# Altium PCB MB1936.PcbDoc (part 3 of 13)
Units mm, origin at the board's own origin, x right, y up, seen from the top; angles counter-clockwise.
Board outline 172 x 137 mm, 6 copper layers (Top Layer, Signal Layer 1, Signal Layer 2, Signal Layer 3, Signal Layer 4, Bottom Layer), stack 1.549 mm thick; 859 components, 672 nets, 3477 pads, 2222 vias.
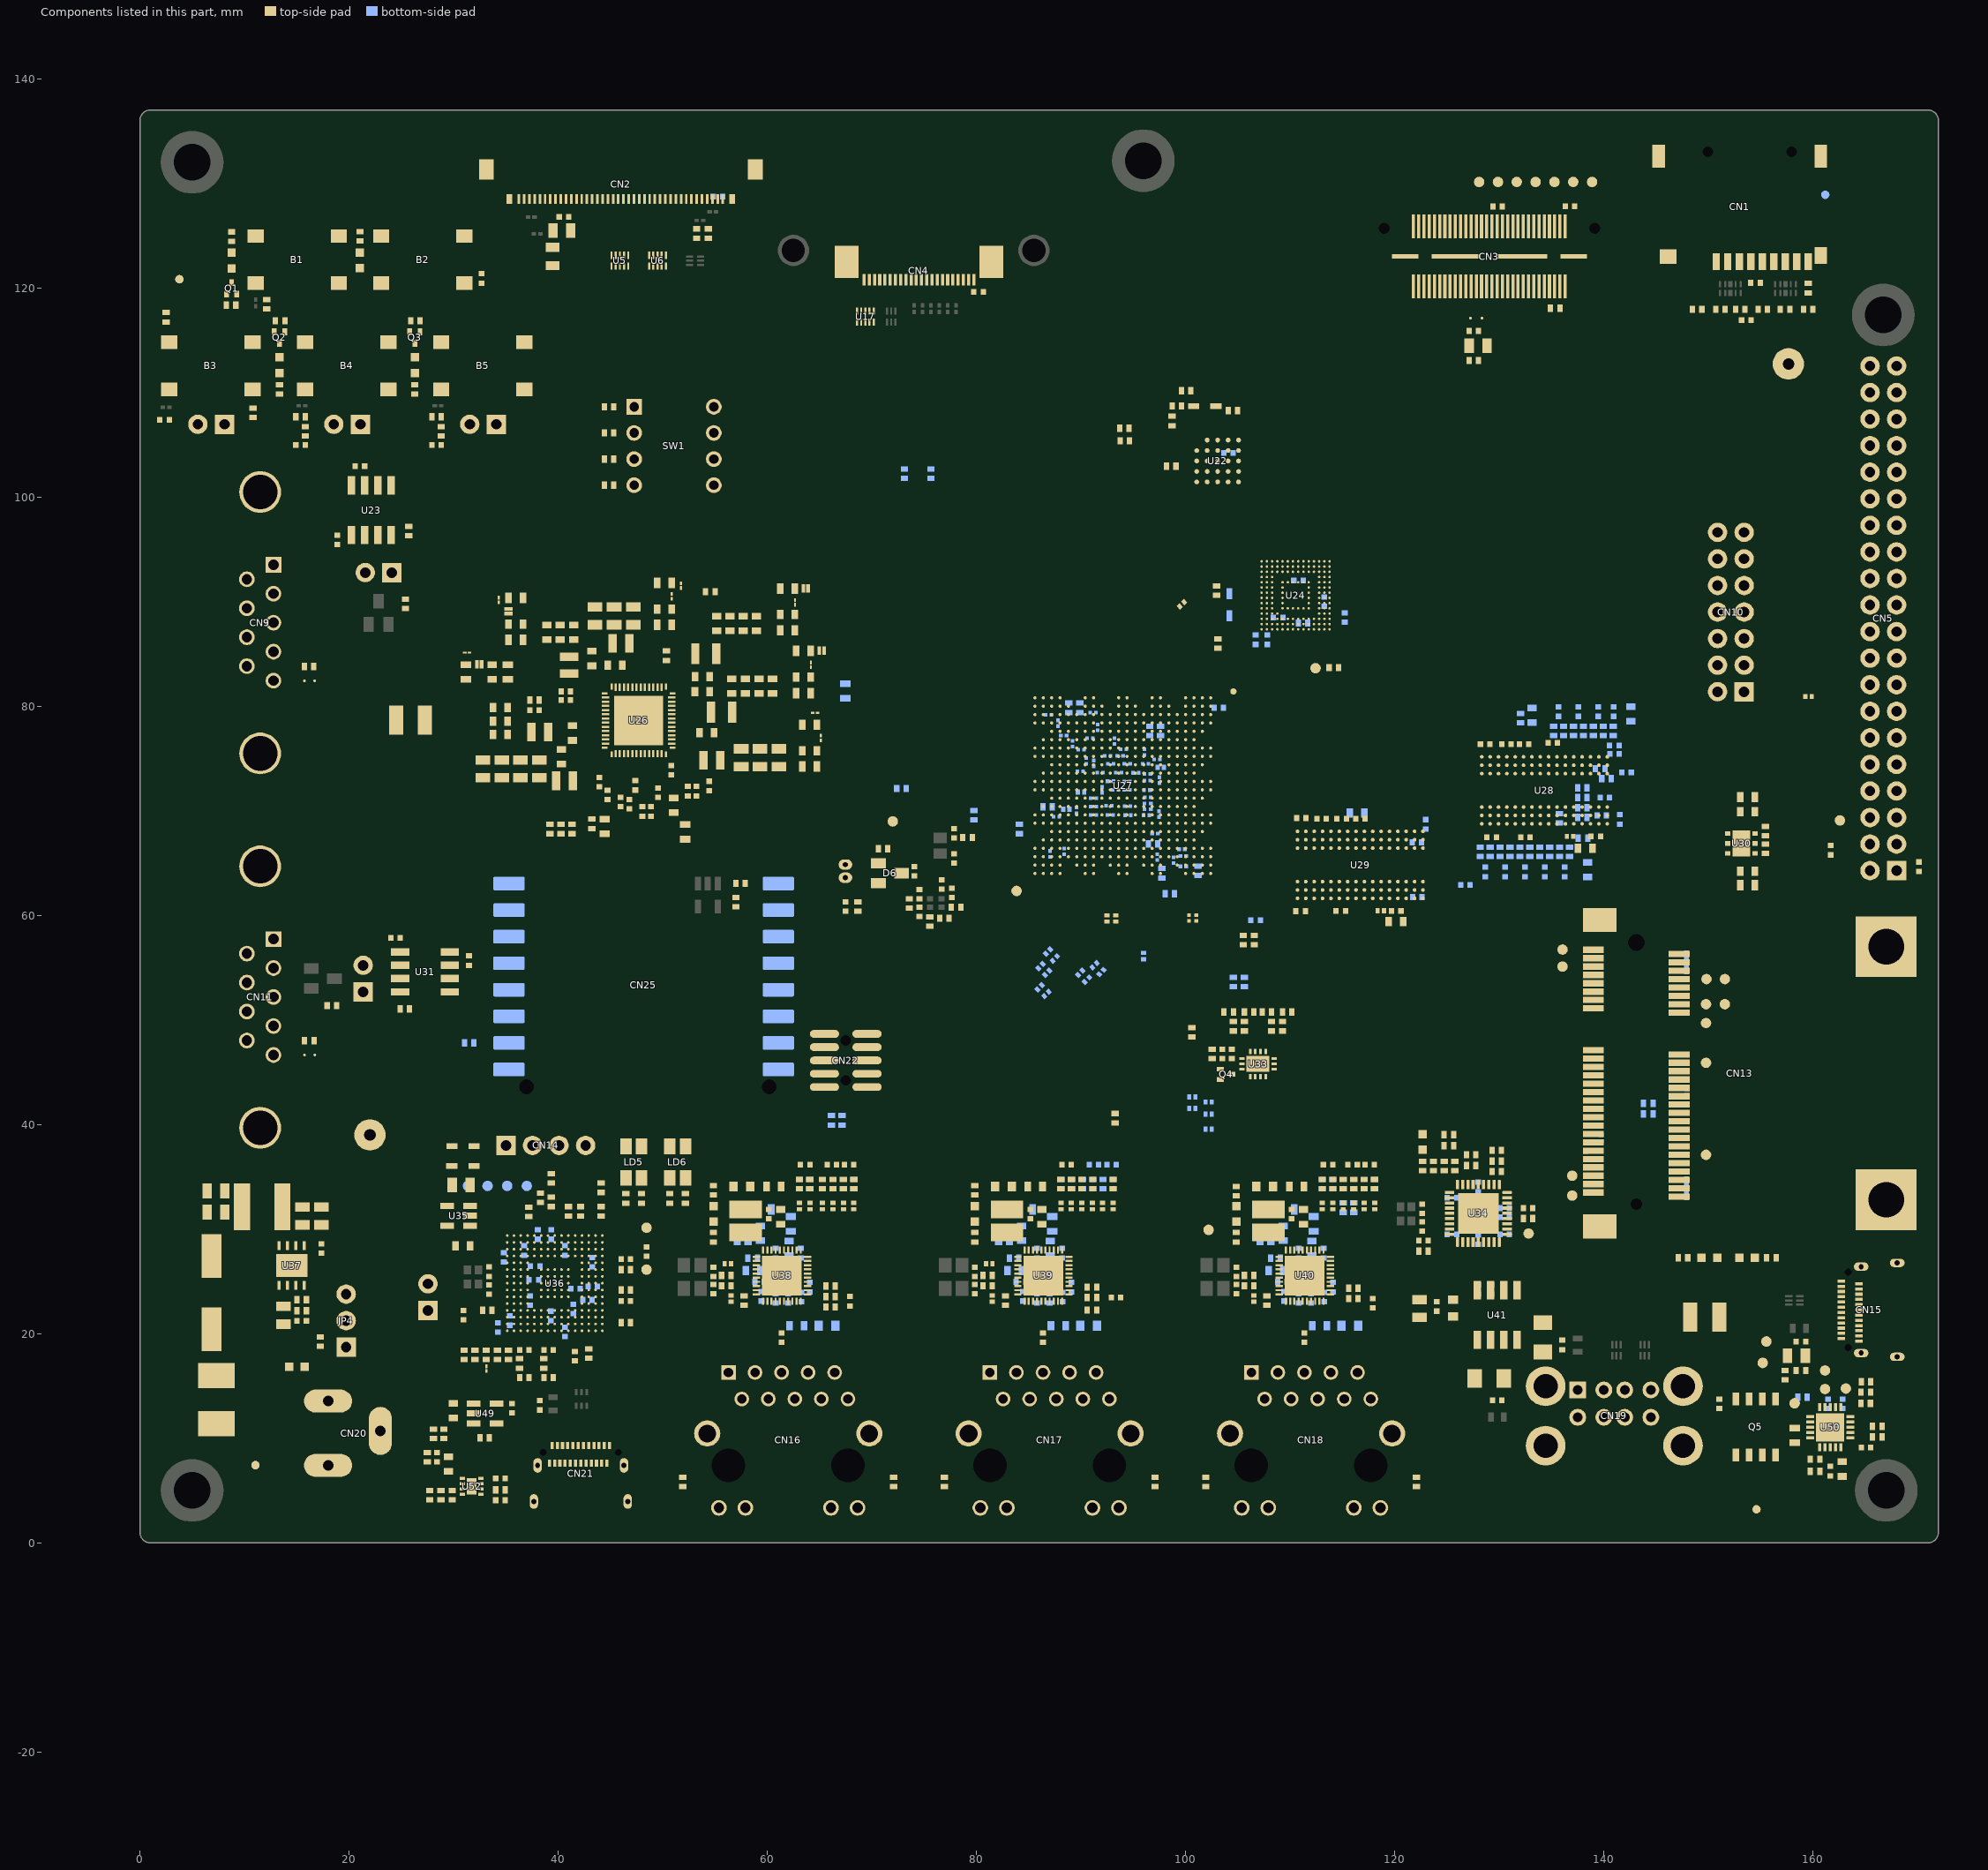
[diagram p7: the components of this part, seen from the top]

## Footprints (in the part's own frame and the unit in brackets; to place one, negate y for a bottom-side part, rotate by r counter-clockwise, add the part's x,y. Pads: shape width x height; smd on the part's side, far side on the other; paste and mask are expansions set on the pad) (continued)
ESD_UQFN-10L_2P25X1P4_P040 [mm] "MCD-03059"
  rect 0.2x0.7 smd mask+0.05: 1(-0.8,-0.525) 2(-0.4,-0.525) 3(0,-0.525) 4(0.4,-0.525) 5(0.8,-0.525) 6(0.8,0.525) 7(0.4,0.525) 8(0,0.525) 9(-0.4,0.525) 10(-0.8,0.525)
  body extent -1.12,-0.7 1.12,0.7, height 0.51
FIL_0603_H0P65 [mm]
  rect 0.8x0.95 smd mask+0.05: 1(-0.8,0) 2(0.8,0)
  silkscreen extent -1.33,-0.6 1.33,0.6, body extent -0.87,-0.47 0.87,0.47, height 0.65
ICC_BGA24_5X5-BALL-ARRAY_6X8_P1 [mm]
  round 0.45 smd mask+0.05: A2(-1,2) A3(0,2) A4(1,2) A5(2,2) B1(-2,1) B2(-1,1) B3(0,1) B4(1,1) B5(2,1) C1(-2,0) C2(-1,0) C3(0,0) C4(1,0) C5(2,0) D1(-2,-1) D2(-1,-1) D3(0,-1) D4(1,-1) D5(2,-1) E1(-2,-2) E2(-1,-2) E3(0,-2) E4(1,-2) E5(2,-2)
  silkscreen extent -3.05,-4.05 3.05,4.05, body extent -3.05,-4.05 3.05,4.05, height 1.2
ICC_DFN6-EPAD_3X3_P095 [mm]
  rect 0.45x0.5 smd mask+0.05: 1(-0.95,-1.3) 2(0,-1.3) 3(0.95,-1.3) 4(0.95,1.3) 5(0,1.3) 6(-0.95,1.3)
  rect 2.5x1.7 smd mask+0.05: EP(0,0)
  silkscreen extent -1.55,-1.55 1.55,1.55, body extent -1.55,-1.55 1.55,1.55, height 1
ICC_FBGA96_TB_7P5X13_P080 [mm] "MCD-03523"
  round 0.35 smd mask+0.05: A1(-3.2,6) A2(-2.4,6) A3(-1.6,6) A7(1.6,6) A8(2.4,6) A9(3.2,6) B1(-3.2,5.2) B2(-2.4,5.2) B3(-1.6,5.2) B7(1.6,5.2) B8(2.4,5.2) B9(3.2,5.2) C1(-3.2,4.4) C2(-2.4,4.4) C3(-1.6,4.4) C7(1.6,4.4) C8(2.4,4.4) C9(3.2,4.4) D1(-3.2,3.6) D2(-2.4,3.6) D3(-1.6,3.6) D7(1.6,3.6) D8(2.4,3.6) D9(3.2,3.6) E1(-3.2,2.8) E2(-2.4,2.8) E3(-1.6,2.8) E7(1.6,2.8) E8(2.4,2.8) E9(3.2,2.8) F1(-3.2,2) F2(-2.4,2) F3(-1.6,2) F7(1.6,2) F8(2.4,2) F9(3.2,2) G1(-3.2,1.2) G2(-2.4,1.2) G3(-1.6,1.2) G7(1.6,1.2) G8(2.4,1.2) G9(3.2,1.2) H1(-3.2,0.4) H2(-2.4,0.4) H3(-1.6,0.4) H7(1.6,0.4) H8(2.4,0.4) H9(3.2,0.4) J1(-3.2,-0.4) J2(-2.4,-0.4) J3(-1.6,-0.4) J7(1.6,-0.4) J8(2.4,-0.4) J9(3.2,-0.4) K1(-3.2,-1.2) K2(-2.4,-1.2) K3(-1.6,-1.2) K7(1.6,-1.2) K8(2.4,-1.2) K9(3.2,-1.2) L1(-3.2,-2) L2(-2.4,-2) L3(-1.6,-2) L7(1.6,-2) L8(2.4,-2) L9(3.2,-2) M1(-3.2,-2.8) M2(-2.4,-2.8) M3(-1.6,-2.8) M7(1.6,-2.8) M8(2.4,-2.8) M9(3.2,-2.8) N1(-3.2,-3.6) N2(-2.4,-3.6) N3(-1.6,-3.6) N7(1.6,-3.6) N8(2.4,-3.6) N9(3.2,-3.6) P1(-3.2,-4.4) P2(-2.4,-4.4) P3(-1.6,-4.4) P7(1.6,-4.4) P8(2.4,-4.4) P9(3.2,-4.4) R1(-3.2,-5.2) R2(-2.4,-5.2) R3(-1.6,-5.2) R7(1.6,-5.2) R8(2.4,-5.2) R9(3.2,-5.2) T1(-3.2,-6) T2(-2.4,-6) T3(-1.6,-6) T7(1.6,-6) T8(2.4,-6) T9(3.2,-6)
  silkscreen extent -3.93,-6.55 3.8,6.68, body extent -3.8,-6.55 3.8,6.55, height 1.21
ICC_LFBGA436_18X18_P080_H1P70_STM32MP257_CODE-B0D1 [mm] "MCD02000"
  round 0.3 smd paste+0.025 mask+0.05: A1(-8.4,8.4) A2(-7.6,8.4) A3(-6.8,8.4) A4(-6,8.4) A7(-3.6,8.4) A8(-2.8,8.4) A11(-0.4,8.4) A12(0.4,8.4) A15(2.8,8.4) A16(3.6,8.4) A19(6,8.4) A20(6.8,8.4) A21(7.6,8.4) A22(8.4,8.4) AA1(-8.4,-7.6) AA2(-7.6,-7.6) AA3(-6.8,-7.6) AA4(-6,-7.6) AA6(-4.4,-7.6) AA7(-3.6,-7.6) AA8(-2.8,-7.6) AA10(-1.2,-7.6) AA11(-0.4,-7.6) AA12(0.4,-7.6) AA14(2,-7.6) AA15(2.8,-7.6) AA16(3.6,-7.6) AA18(5.2,-7.6) AA19(6,-7.6) AA20(6.8,-7.6) AA21(7.6,-7.6) AA22(8.4,-7.6) AB1(-8.4,-8.4) AB2(-7.6,-8.4) AB3(-6.8,-8.4) AB4(-6,-8.4) AB7(-3.6,-8.4) AB8(-2.8,-8.4) AB11(-0.4,-8.4) AB12(0.4,-8.4) AB15(2.8,-8.4) AB16(3.6,-8.4) AB19(6,-8.4) AB20(6.8,-8.4) AB21(7.6,-8.4) AB22(8.4,-8.4) B1(-8.4,7.6) B2(-7.6,7.6) B3(-6.8,7.6) B4(-6,7.6) B5(-5.2,7.6) B7(-3.6,7.6) B8(-2.8,7.6) B9(-2,7.6) B11(-0.4,7.6) B12(0.4,7.6) B13(1.2,7.6) B15(2.8,7.6) B16(3.6,7.6) B17(4.4,7.6) B19(6,7.6) B20(6.8,7.6) B21(7.6,7.6) B22(8.4,7.6) C1(-8.4,6.8) C2(-7.6,6.8) C3(-6.8,6.8) C4(-6,6.8) C5(-5.2,6.8) C6(-4.4,6.8) C7(-3.6,6.8) C8(-2.8,6.8) C9(-2,6.8) C10(-1.2,6.8) C11(-0.4,6.8) C12(0.4,6.8) C13(1.2,6.8) C14(2,6.8) C15(2.8,6.8) C16(3.6,6.8) C17(4.4,6.8) C18(5.2,6.8) C19(6,6.8) C20(6.8,6.8) C21(7.6,6.8) C22(8.4,6.8) D1(-8.4,6) D2(-7.6,6) D3(-6.8,6) D4(-6,6) D5(-5.2,6) D6(-4.4,6) D7(-3.6,6) D8(-2.8,6) D9(-2,6) D10(-1.2,6) D11(-0.4,6) D12(0.4,6) D13(1.2,6) D14(2,6) D15(2.8,6) D16(3.6,6) D17(4.4,6) D18(5.2,6) D19(6,6) D20(6.8,6) D21(7.6,6) D22(8.4,6) E3(-6.8,5.2) E4(-6,5.2) E5(-5.2,5.2) E6(-4.4,5.2) E7(-3.6,5.2) E8(-2.8,5.2) E9(-2,5.2) E10(-1.2,5.2) E11(-0.4,5.2) E12(0.4,5.2) E13(1.2,5.2) E14(2,5.2) E15(2.8,5.2) E16(3.6,5.2) E17(4.4,5.2) E18(5.2,5.2) E19(6,5.2) E20(6.8,5.2) E21(7.6,5.2) F2(-7.6,4.4) F3(-6.8,4.4) F4(-6,4.4) F5(-5.2,4.4) F6(-4.4,4.4) F7(-3.6,4.4) F8(-2.8,4.4) F9(-2,4.4) F10(-1.2,4.4) F11(-0.4,4.4) F12(0.4,4.4) F13(1.2,4.4) F14(2,4.4) F15(2.8,4.4) F16(3.6,4.4) F17(4.4,4.4) F18(5.2,4.4) F19(6,4.4) F20(6.8,4.4) G1(-8.4,3.6) G2(-7.6,3.6) G3(-6.8,3.6) G4(-6,3.6) G5(-5.2,3.6) G6(-4.4,3.6) G7(-3.6,3.6) G8(-2.8,3.6) G9(-2,3.6) G10(-1.2,3.6) G11(-0.4,3.6) G12(0.4,3.6) G13(1.2,3.6) G14(2,3.6) G15(2.8,3.6) G16(3.6,3.6) G17(4.4,3.6) G18(5.2,3.6) G19(6,3.6) G20(6.8,3.6) G21(7.6,3.6) G22(8.4,3.6) H1(-8.4,2.8) H2(-7.6,2.8) H3(-6.8,2.8) H4(-6,2.8) H5(-5.2,2.8) H6(-4.4,2.8) H7(-3.6,2.8) H8(-2.8,2.8) H9(-2,2.8) H10(-1.2,2.8) H11(-0.4,2.8) H12(0.4,2.8) H13(1.2,2.8) H14(2,2.8) H15(2.8,2.8) H16(3.6,2.8) H17(4.4,2.8) H18(5.2,2.8) H19(6,2.8) H20(6.8,2.8) H21(7.6,2.8) H22(8.4,2.8) J3(-6.8,2) J4(-6,2) J5(-5.2,2) J6(-4.4,2) J7(-3.6,2) J8(-2.8,2) J9(-2,2) J10(-1.2,2) J11(-0.4,2) J12(0.4,2) J13(1.2,2) J14(2,2) J15(2.8,2) J16(3.6,2) J17(4.4,2) J18(5.2,2) J19(6,2) J20(6.8,2) J21(7.6,2) K2(-7.6,1.2) K3(-6.8,1.2) K4(-6,1.2) K5(-5.2,1.2) K6(-4.4,1.2) K7(-3.6,1.2) K8(-2.8,1.2) K9(-2,1.2) K10(-1.2,1.2) K11(-0.4,1.2) K12(0.4,1.2) K13(1.2,1.2) K14(2,1.2) K15(2.8,1.2) K16(3.6,1.2) K17(4.4,1.2) K18(5.2,1.2) K19(6,1.2) K20(6.8,1.2) L1(-8.4,0.4) L2(-7.6,0.4) L3(-6.8,0.4) L4(-6,0.4) L5(-5.2,0.4) L6(-4.4,0.4) L7(-3.6,0.4) L8(-2.8,0.4) L9(-2,0.4) L10(-1.2,0.4) L11(-0.4,0.4) L12(0.4,0.4) L13(1.2,0.4) L14(2,0.4) L15(2.8,0.4) L16(3.6,0.4) L17(4.4,0.4) L18(5.2,0.4) L19(6,0.4) L20(6.8,0.4) L21(7.6,0.4) L22(8.4,0.4) M1(-8.4,-0.4) M2(-7.6,-0.4) M3(-6.8,-0.4) M4(-6,-0.4) M5(-5.2,-0.4) M6(-4.4,-0.4) M7(-3.6,-0.4) M8(-2.8,-0.4) M9(-2,-0.4) M10(-1.2,-0.4) M11(-0.4,-0.4) M12(0.4,-0.4) M13(1.2,-0.4) M14(2,-0.4) M15(2.8,-0.4) M16(3.6,-0.4) M17(4.4,-0.4) M18(5.2,-0.4) M19(6,-0.4) M20(6.8,-0.4) M21(7.6,-0.4) M22(8.4,-0.4) N3(-6.8,-1.2) N4(-6,-1.2) N5(-5.2,-1.2) N6(-4.4,-1.2) N7(-3.6,-1.2) N8(-2.8,-1.2) N9(-2,-1.2) N10(-1.2,-1.2) N11(-0.4,-1.2) N12(0.4,-1.2) N13(1.2,-1.2) N14(2,-1.2) N15(2.8,-1.2) N16(3.6,-1.2) N17(4.4,-1.2) N18(5.2,-1.2) N19(6,-1.2) N20(6.8,-1.2) N21(7.6,-1.2) P2(-7.6,-2) P3(-6.8,-2) P4(-6,-2) P5(-5.2,-2) P6(-4.4,-2) P7(-3.6,-2) P8(-2.8,-2) P9(-2,-2) P10(-1.2,-2) P11(-0.4,-2) P12(0.4,-2) P13(1.2,-2) P14(2,-2) P15(2.8,-2) P16(3.6,-2) P17(4.4,-2) P18(5.2,-2) P19(6,-2) P20(6.8,-2) R1(-8.4,-2.8) R2(-7.6,-2.8) R3(-6.8,-2.8) R4(-6,-2.8) R5(-5.2,-2.8) R6(-4.4,-2.8) R7(-3.6,-2.8) R8(-2.8,-2.8) R9(-2,-2.8) R10(-1.2,-2.8) R11(-0.4,-2.8) R12(0.4,-2.8) R13(1.2,-2.8) R14(2,-2.8) R15(2.8,-2.8) R16(3.6,-2.8) R17(4.4,-2.8) R18(5.2,-2.8) R19(6,-2.8) R20(6.8,-2.8) R21(7.6,-2.8) R22(8.4,-2.8) T1(-8.4,-3.6) T2(-7.6,-3.6) T3(-6.8,-3.6) T4(-6,-3.6) T5(-5.2,-3.6) T6(-4.4,-3.6) T7(-3.6,-3.6) T8(-2.8,-3.6) T9(-2,-3.6) T10(-1.2,-3.6) T11(-0.4,-3.6) T12(0.4,-3.6) T13(1.2,-3.6) T14(2,-3.6) T15(2.8,-3.6) T16(3.6,-3.6) T17(4.4,-3.6) T18(5.2,-3.6) T19(6,-3.6) T20(6.8,-3.6) T21(7.6,-3.6) T22(8.4,-3.6) U3(-6.8,-4.4) U4(-6,-4.4) U5(-5.2,-4.4) U6(-4.4,-4.4) U7(-3.6,-4.4) U8(-2.8,-4.4) U9(-2,-4.4) U10(-1.2,-4.4) U11(-0.4,-4.4) U12(0.4,-4.4) U13(1.2,-4.4) U14(2,-4.4) U15(2.8,-4.4) U16(3.6,-4.4) U17(4.4,-4.4) U18(5.2,-4.4) U19(6,-4.4) U20(6.8,-4.4) U21(7.6,-4.4) V2(-7.6,-5.2) V3(-6.8,-5.2) V4(-6,-5.2) V5(-5.2,-5.2) V6(-4.4,-5.2) V7(-3.6,-5.2) V8(-2.8,-5.2) V9(-2,-5.2) V10(-1.2,-5.2) V11(-0.4,-5.2) V12(0.4,-5.2) V13(1.2,-5.2) V14(2,-5.2) V15(2.8,-5.2) V16(3.6,-5.2) V17(4.4,-5.2) V18(5.2,-5.2) V19(6,-5.2) V20(6.8,-5.2) W1(-8.4,-6) W2(-7.6,-6) W3(-6.8,-6) W4(-6,-6) W5(-5.2,-6) W6(-4.4,-6) W7(-3.6,-6) W8(-2.8,-6) W9(-2,-6) W10(-1.2,-6) W11(-0.4,-6) W12(0.4,-6) W13(1.2,-6) W14(2,-6) W15(2.8,-6) W16(3.6,-6) W17(4.4,-6) W18(5.2,-6) W19(6,-6) W20(6.8,-6) W21(7.6,-6) W22(8.4,-6) Y1(-8.4,-6.8) Y2(-7.6,-6.8) Y3(-6.8,-6.8) Y4(-6,-6.8) Y5(-5.2,-6.8) Y6(-4.4,-6.8) Y7(-3.6,-6.8) Y8(-2.8,-6.8) Y9(-2,-6.8) Y10(-1.2,-6.8) Y11(-0.4,-6.8) Y12(0.4,-6.8) Y13(1.2,-6.8) Y14(2,-6.8) Y15(2.8,-6.8) Y16(3.6,-6.8) Y17(4.4,-6.8) Y18(5.2,-6.8) Y19(6,-6.8) Y20(6.8,-6.8) Y21(7.6,-6.8) Y22(8.4,-6.8)
  silkscreen extent -9.25,-9.1 9.1,9.25, body extent -9.1,-9.1 9.1,9.1, height 1.7
ICC_P-WFBGA153_13X11P5_P050 [mm]
  round 0.23 smd mask+0.05: A1(-3.25,-3.25) A2(-3.25,-2.75) A3(-3.25,-2.25) A4(-3.25,-1.75) A5(-3.25,-1.25) A6(-3.25,-0.75) A7(-3.25,-0.25) A8(-3.25,0.25) A9(-3.25,0.75) A10(-3.25,1.25) A11(-3.25,1.75) A12(-3.25,2.25) A13(-3.25,2.75) A14(-3.25,3.25) B1(-2.75,-3.25) B2(-2.75,-2.75) B3(-2.75,-2.25) B4(-2.75,-1.75) B5(-2.75,-1.25) B6(-2.75,-0.75) B7(-2.75,-0.25) B8(-2.75,0.25) B9(-2.75,0.75) B10(-2.75,1.25) B11(-2.75,1.75) B12(-2.75,2.25) B13(-2.75,2.75) B14(-2.75,3.25) C1(-2.25,-3.25) C2(-2.25,-2.75) C3(-2.25,-2.25) C4(-2.25,-1.75) C5(-2.25,-1.25) C6(-2.25,-0.75) C7(-2.25,-0.25) C8(-2.25,0.25) C9(-2.25,0.75) C10(-2.25,1.25) C11(-2.25,1.75) C12(-2.25,2.25) C13(-2.25,2.75) C14(-2.25,3.25) D1(-1.75,-3.25) D2(-1.75,-2.75) D3(-1.75,-2.25) D4(-1.75,-1.75) D12(-1.75,2.25) D13(-1.75,2.75) D14(-1.75,3.25) E1(-1.25,-3.25) E2(-1.25,-2.75) E3(-1.25,-2.25) E5(-1.25,-1.25) E6(-1.25,-0.75) E7(-1.25,-0.25) E8(-1.25,0.25) E9(-1.25,0.75) E10(-1.25,1.25) E12(-1.25,2.25) E13(-1.25,2.75) E14(-1.25,3.25) F1(-0.75,-3.25) F2(-0.75,-2.75) F3(-0.75,-2.25) F5(-0.75,-1.25) F10(-0.75,1.25) F12(-0.75,2.25) F13(-0.75,2.75) F14(-0.75,3.25) G1(-0.25,-3.25) G2(-0.25,-2.75) G3(-0.25,-2.25) G5(-0.25,-1.25) G10(-0.25,1.25) G12(-0.25,2.25) G13(-0.25,2.75) G14(-0.25,3.25) H1(0.25,-3.25) H2(0.25,-2.75) H3(0.25,-2.25) H5(0.25,-1.25) H10(0.25,1.25) H12(0.25,2.25) H13(0.25,2.75) H14(0.25,3.25) J1(0.75,-3.25) J2(0.75,-2.75) J3(0.75,-2.25) J5(0.75,-1.25) J10(0.75,1.25) J12(0.75,2.25) J13(0.75,2.75) J14(0.75,3.25) K1(1.25,-3.25) K2(1.25,-2.75) K3(1.25,-2.25) K5(1.25,-1.25) K6(1.25,-0.75) K7(1.25,-0.25) K8(1.25,0.25) K9(1.25,0.75) K10(1.25,1.25) K12(1.25,2.25) K13(1.25,2.75) K14(1.25,3.25) L1(1.75,-3.25) L2(1.75,-2.75) L3(1.75,-2.25) L12(1.75,2.25) L13(1.75,2.75) L14(1.75,3.25) M1(2.25,-3.25) M2(2.25,-2.75) M3(2.25,-2.25) M4(2.25,-1.75) M5(2.25,-1.25) M6(2.25,-0.75) M7(2.25,-0.25) M8(2.25,0.25) M9(2.25,0.75) M10(2.25,1.25) M11(2.25,1.75) M12(2.25,2.25) M13(2.25,2.75) M14(2.25,3.25) N1(2.75,-3.25) N2(2.75,-2.75) N3(2.75,-2.25) N4(2.75,-1.75) N5(2.75,-1.25) N6(2.75,-0.75) N7(2.75,-0.25) N8(2.75,0.25) N9(2.75,0.75) N10(2.75,1.25) N11(2.75,1.75) N12(2.75,2.25) N13(2.75,2.75) N14(2.75,3.25) P1(3.25,-3.25) P2(3.25,-2.75) P3(3.25,-2.25) P4(3.25,-1.75) P5(3.25,-1.25) P6(3.25,-0.75) P7(3.25,-0.25) P8(3.25,0.25) P9(3.25,0.75) P10(3.25,1.25) P11(3.25,1.75) P12(3.25,2.25) P13(3.25,2.75) P14(3.25,3.25)
  silkscreen extent -6.78,-6.02 6.63,5.87, body extent -6.55,-5.8 6.55,5.8, height 1
ICC_QFN14-EPAD_3P2X2P5_P050 [mm] "MCD-02349"
  rect 0.25x0.5 smd mask+0.05: 1(-0.75,-1.2) 2(-0.25,-1.2) 3(0.25,-1.2) 4(0.75,-1.2) 8(0.75,1.2) 9(0.25,1.2) 10(-0.25,1.2) 11(-0.75,1.2)
  rect 0.5x0.25 smd mask+0.05: 5(1.55,-0.5) 6(1.55,0) 7(1.55,0.5) 12(-1.55,0.5) 13(-1.55,0) 14(-1.55,-0.5)
  rect 2.2x1.5 smd mask+0.05: 15(0,0)
  silkscreen extent -1.8,-1.45 1.63,1.28, body extent -1.63,-1.28 1.63,1.28, height 0.86
ICC_QFN20-EPAD_4X4_P050 [mm] "MCD-02130"
  rect 0.75x0.3 smd mask+0.05: 1(-1.925,1) 2(-1.925,0.5) 3(-1.925,0) 4(-1.925,-0.5) 5(-1.925,-1) 11(1.925,-1) 12(1.925,-0.5) 13(1.925,0) 14(1.925,0.5) 15(1.925,1)
  rect 0.3x0.75 smd mask+0.05: 6(-1,-1.925) 7(-0.5,-1.925) 8(0,-1.925) 9(0.5,-1.925) 10(1,-1.925) 16(1,1.925) 17(0.5,1.925) 18(0,1.925) 19(-0.5,1.925) 20(-1,1.925)
  rect 2.7x2.7 smd mask+0.05: 21(0,0)
  silkscreen extent -2.07,-2.07 2.07,2.07, body extent -2.13,-2.13 2.13,2.13, height 1.01
ICC_QFN36-EPAD_6X6_P050 [mm]
  rrect50% 0.3x0.9 smd mask+0.05: 1(-2,-2.75) 9(2,-2.75) 19(2,2.75) 27(-2,2.75)
  rect 0.3x0.9 smd mask+0.05: 2(-1.5,-2.75) 3(-1,-2.75) 4(-0.5,-2.75) 5(0,-2.75) 6(0.5,-2.75) 7(1,-2.75) 8(1.5,-2.75) 20(1.5,2.75) 21(1,2.75) 22(0.5,2.75) 23(0,2.75) 24(-0.5,2.75) 25(-1,2.75) 26(-1.5,2.75)
  rrect50% 0.9x0.3 smd mask+0.05: 10(2.75,-2) 18(2.75,2) 28(-2.75,2) 36(-2.75,-2)
  rect 0.9x0.3 smd mask+0.05: 11(2.75,-1.5) 12(2.75,-1) 13(2.75,-0.5) 14(2.75,0) 15(2.75,0.5) 16(2.75,1) 17(2.75,1.5) 29(-2.75,1.5) 30(-2.75,1) 31(-2.75,0.5) 32(-2.75,0) 33(-2.75,-0.5) 34(-2.75,-1) 35(-2.75,-1.5)
  rect 3.9x3.9 smd mask+0.05: 37(0,0)
  silkscreen extent -3.15,-3.15 3.15,3.15, body extent -3.06,-3.06 3.06,3.06, height 1
ICC_QFN40-EPAD_5X5_P040 [mm]
  rect 0.7x0.2 smd mask+0.05: 1(-2.45,1.8) 2(-2.45,1.4) 3(-2.45,1) 4(-2.45,0.6) 5(-2.45,0.2) 6(-2.45,-0.2) 7(-2.45,-0.6) 8(-2.45,-1) 9(-2.45,-1.4) 10(-2.45,-1.8) 21(2.45,-1.8) 22(2.45,-1.4) 23(2.45,-1) 24(2.45,-0.6) 25(2.45,-0.2) 26(2.45,0.2) 27(2.45,0.6) 28(2.45,1) 29(2.45,1.4) 30(2.45,1.8)
  rect 0.2x0.7 smd mask+0.05: 11(-1.8,-2.45) 12(-1.4,-2.45) 13(-1,-2.45) 14(-0.6,-2.45) 15(-0.2,-2.45) 16(0.2,-2.45) 17(0.6,-2.45) 18(1,-2.45) 19(1.4,-2.45) 20(1.8,-2.45) 31(1.8,2.45) 32(1.4,2.45) 33(1,2.45) 34(0.6,2.45) 35(0.2,2.45) 36(-0.2,2.45) 37(-0.6,2.45) 38(-1,2.45) 39(-1.4,2.45) 40(-1.8,2.45)
  rect 3.8x3.8 smd mask+0.05: 41(0,0)
  silkscreen extent -2.5,-2.5 2.5,2.5, body extent -2.5,-2.5 2.5,2.5, height 0.91
ICC_QFN56-EPAD_6P5X6P5_P040 [mm] "MCD-03000"
  rect 0.55x0.21 smd mask+0.05: 1(-3.245,2.6) 14(-3.245,-2.6) 29(3.245,-2.6) 42(3.245,2.6)
  rect 0.7x0.21 smd mask+0.05: 2(-3.17,2.2) 3(-3.17,1.8) 4(-3.17,1.4) 5(-3.17,1) 6(-3.17,0.6) 7(-3.17,0.2) 8(-3.17,-0.2) 9(-3.17,-0.6) 10(-3.17,-1) 11(-3.17,-1.4) 12(-3.17,-1.8) 13(-3.17,-2.2) 30(3.17,-2.2) 31(3.17,-1.8) 32(3.17,-1.4) 33(3.17,-1) 34(3.17,-0.6) 35(3.17,-0.2) 36(3.17,0.2) 37(3.17,0.6) 38(3.17,1) 39(3.17,1.4) 40(3.17,1.8) 41(3.17,2.2)
  rect 0.21x0.55 smd mask+0.05: 15(-2.6,-3.245) 28(2.6,-3.245) 43(2.6,3.245) 56(-2.6,3.245)
  rect 0.21x0.7 smd mask+0.05: 16(-2.2,-3.17) 17(-1.8,-3.17) 18(-1.4,-3.17) 19(-1,-3.17) 20(-0.6,-3.17) 21(-0.2,-3.17) 22(0.2,-3.17) 23(0.6,-3.17) 24(1,-3.17) 25(1.4,-3.17) 26(1.8,-3.17) 27(2.2,-3.17) 44(2.2,3.17) 45(1.8,3.17) 46(1.4,3.17) 47(1,3.17) 48(0.6,3.17) 49(0.2,3.17) 50(-0.2,3.17) 51(-0.6,3.17) 52(-1,3.17) 53(-1.4,3.17) 54(-1.8,3.17) 55(-2.2,3.17)
  rect 4.7x4.7 smd mask+0.05: 57(0,0)
  Top Layer region: -2.97,2.495 -2.82,2.495 -2.82,2.555 -2.97,2.705
  Top Layer region: -2.97,-2.495 -2.82,-2.495 -2.82,-2.555 -2.97,-2.705
  Top Layer region: -2.495,2.97 -2.495,2.82 -2.555,2.82 -2.705,2.97
  Top Layer region: 2.97,-2.495 2.82,-2.495 2.82,-2.555 2.97,-2.705
  Top Layer region: 2.495,-2.97 2.495,-2.82 2.555,-2.82 2.705,-2.97
  Top Layer region: 2.97,2.495 2.82,2.495 2.82,2.555 2.97,2.705
  Top Layer region: 2.495,2.97 2.495,2.82 2.555,2.82 2.705,2.97
  Top Layer region: -2.495,-2.97 -2.495,-2.82 -2.555,-2.82 -2.705,-2.97
  silkscreen extent -3.44,3 -3.01,3.42, body extent -3.25,-3.25 3.25,3.25, height 0.91
ICC_SO8_5X4_P127 [mm]
  rect 0.7x1.75 smd mask+0.05: 1(-1.905,-2.375) 2(-0.635,-2.375) 3(0.635,-2.375) 4(1.905,-2.375) 5(1.905,2.375) 6(0.635,2.375) 7(-0.635,2.375) 8(-1.905,2.375)
  silkscreen extent -2.73,-3.25 2.58,2, body extent -2.57,-3 2.57,3, height 1.75
ICC_SOT23-5L_H1P45 [mm]
  rect 0.6x1.3 smd mask+0.05: 1(-0.95,-1.1) 2(0,-1.1) 3(0.95,-1.1) 4(0.95,1.1) 5(-0.95,1.1)
  silkscreen extent -1.75,-1.68 1.6,0.97, body extent -1.52,-1.25 1.52,1.25, height 1.45
ICC_UFBGA201_176+25_10X10_P065 [mm] "IPC"
  round 0.25 smd mask+0.05: A1(-4.55,4.55) A2(-3.9,4.55) A3(-3.25,4.55) A4(-2.6,4.55) A5(-1.95,4.55) A6(-1.3,4.55) A7(-0.65,4.55) A8(0,4.55) A9(0.65,4.55) A10(1.3,4.55) A11(1.95,4.55) A12(2.6,4.55) A13(3.25,4.55) A14(3.9,4.55) A15(4.55,4.55) B1(-4.55,3.9) B2(-3.9,3.9) B3(-3.25,3.9) B4(-2.6,3.9) B5(-1.95,3.9) B6(-1.3,3.9) B7(-0.65,3.9) B8(0,3.9) B9(0.65,3.9) B10(1.3,3.9) B11(1.95,3.9) B12(2.6,3.9) B13(3.25,3.9) B14(3.9,3.9) B15(4.55,3.9) C1(-4.55,3.25) C2(-3.9,3.25) C3(-3.25,3.25) C4(-2.6,3.25) C5(-1.95,3.25) C6(-1.3,3.25) C7(-0.65,3.25) C8(0,3.25) C9(0.65,3.25) C10(1.3,3.25) C11(1.95,3.25) C12(2.6,3.25) C13(3.25,3.25) C14(3.9,3.25) C15(4.55,3.25) D1(-4.55,2.6) D2(-3.9,2.6) D3(-3.25,2.6) D4(-2.6,2.6) D5(-1.95,2.6) D6(-1.3,2.6) D7(-0.65,2.6) D8(0,2.6) D9(0.65,2.6) D10(1.3,2.6) D11(1.95,2.6) D12(2.6,2.6) D13(3.25,2.6) D14(3.9,2.6) D15(4.55,2.6) E1(-4.55,1.95) E2(-3.9,1.95) E3(-3.25,1.95) E4(-2.6,1.95) E12(2.6,1.95) E13(3.25,1.95) E14(3.9,1.95) E15(4.55,1.95) F1(-4.55,1.3) F2(-3.9,1.3) F3(-3.25,1.3) F4(-2.6,1.3) F6(-1.3,1.3) F7(-0.65,1.3) F8(0,1.3) F9(0.65,1.3) F10(1.3,1.3) F12(2.6,1.3) F13(3.25,1.3) F14(3.9,1.3) F15(4.55,1.3) G1(-4.55,0.65) G2(-3.9,0.65) G3(-3.25,0.65) G4(-2.6,0.65) G6(-1.3,0.65) G7(-0.65,0.65) G8(0,0.65) G9(0.65,0.65) G10(1.3,0.65) G12(2.6,0.65) G13(3.25,0.65) G14(3.9,0.65) G15(4.55,0.65) H1(-4.55,0) H2(-3.9,0) H3(-3.25,0) H4(-2.6,0) H6(-1.3,0) H7(-0.65,0) H8(0,0) H9(0.65,0) H10(1.3,0) H12(2.6,0) H13(3.25,0) H14(3.9,0) H15(4.55,0) J1(-4.55,-0.65) J2(-3.9,-0.65) J3(-3.25,-0.65) J4(-2.6,-0.65) J6(-1.3,-0.65) J7(-0.65,-0.65) J8(0,-0.65) J9(0.65,-0.65) J10(1.3,-0.65) J12(2.6,-0.65) J13(3.25,-0.65) J14(3.9,-0.65) J15(4.55,-0.65) K1(-4.55,-1.3) K2(-3.9,-1.3) K3(-3.25,-1.3) K4(-2.6,-1.3) K6(-1.3,-1.3) K7(-0.65,-1.3) K8(0,-1.3) K9(0.65,-1.3) K10(1.3,-1.3) K12(2.6,-1.3) K13(3.25,-1.3) K14(3.9,-1.3) K15(4.55,-1.3) L1(-4.55,-1.95) L2(-3.9,-1.95) L3(-3.25,-1.95) L4(-2.6,-1.95) L12(2.6,-1.95) L13(3.25,-1.95) L14(3.9,-1.95) L15(4.55,-1.95) M1(-4.55,-2.6) M2(-3.9,-2.6) M3(-3.25,-2.6) M4(-2.6,-2.6) M5(-1.95,-2.6) M6(-1.3,-2.6) M7(-0.65,-2.6) M8(0,-2.6) M9(0.65,-2.6) M10(1.3,-2.6) M11(1.95,-2.6) M12(2.6,-2.6) M13(3.25,-2.6) M14(3.9,-2.6) M15(4.55,-2.6) N1(-4.55,-3.25) N2(-3.9,-3.25) N3(-3.25,-3.25) N4(-2.6,-3.25) N5(-1.95,-3.25) N6(-1.3,-3.25) N7(-0.65,-3.25) N8(0,-3.25) N9(0.65,-3.25) N10(1.3,-3.25) N11(1.95,-3.25) N12(2.6,-3.25) N13(3.25,-3.25) N14(3.9,-3.25) N15(4.55,-3.25) P1(-4.55,-3.9) P2(-3.9,-3.9) P3(-3.25,-3.9) P4(-2.6,-3.9) P5(-1.95,-3.9) P6(-1.3,-3.9) P7(-0.65,-3.9) P8(0,-3.9) P9(0.65,-3.9) P10(1.3,-3.9) P11(1.95,-3.9) P12(2.6,-3.9) P13(3.25,-3.9) P14(3.9,-3.9) P15(4.55,-3.9) R1(-4.55,-4.55) R2(-3.9,-4.55) R3(-3.25,-4.55) R4(-2.6,-4.55) R5(-1.95,-4.55) R6(-1.3,-4.55) R7(-0.65,-4.55) R8(0,-4.55) R9(0.65,-4.55) R10(1.3,-4.55) R11(1.95,-4.55) R12(2.6,-4.55) R13(3.25,-4.55) R14(3.9,-4.55) R15(4.55,-4.55)
  silkscreen extent -5.22,-5.07 5.07,5.23, body extent -5.07,-5.07 5.07,5.07, height 0.61
ICC_VFQFPN8-EPAD_4X4_P080 [mm] "MCD-02219"
  rect 0.3x0.85 smd mask+0.05: 1(-1.2,-1.9) 2(-0.4,-1.9) 3(0.4,-1.9) 4(1.2,-1.9) 5(1.2,1.9) 6(0.4,1.9) 7(-0.4,1.9) 8(-1.2,1.9)
  rect 3x2.2 smd mask+0.05: 9(0,0)
  silkscreen extent -2,-2 2,2, body extent -2,-2 2,2, height 1.1
ICC_WSON8-EPAD_2X2_P050 [mm] "MCD-02194"
  rect 0.5x0.3 smd paste+0 mask+0.05: 1(-0.9,0.75) 2(-0.9,0.25) 3(-0.9,-0.25) 4(-0.9,-0.75) 5(0.9,-0.75) 6(0.9,-0.25) 7(0.9,0.25) 8(0.9,0.75)
  rect 0.9x1.6 smd paste+0 mask+0.05: 9(0,0)
  silkscreen extent -0.5,-1 0.5,1, body extent -1,-1 1,1, height 0.81
IND_2016_MURATA_LQM2MPN2R2NG0 [mm]
  rect 0.8x1.8 smd mask+0.05: 1(-0.8,0) 2(0.8,0)
  silkscreen extent -0.28,-0.87 0.28,0.87, body extent -1.07,-0.87 1.08,0.87, height 1
IND_2520_TOKO_DFE252012P [mm]
  rect 0.8x2 smd mask+0.05: 1(-1,0) 2(1,0)
  silkscreen extent -1.35,-1.12 1.35,1.12, body extent -1.35,-1.1 1.35,1.1, height 2
IND_5040_WURTH_74404054033 [mm] "MCD-02220"
  rect 1.55x4.5 smd mask+0.05: 1(1.925,0) 2(-1.925,0)
  silkscreen extent -1.5,-2.5 1.5,2.5, body extent -2.6,-2.5 2.6,2.5, height 4
L1210_LQH [mm]
  rect 1.7x3.1 smd mask+0.05: 1(-1.1,0) 2(1.1,0)
  silkscreen extent -2.05,-1.65 2.05,1.65, body extent -1.75,-1.35 1.75,1.35, height 2
LED_0603_OSRAM_LB-Q39G-L2OO-35-1_BLUE_1A2K_H0P4 [mm]
  rect 0.8x0.8 smd mask+0.05: 1(-0.75,0) 2(0.75,0)
  Top Layer keep-out region: -0.35,-0.401 0.35,-0.401 0.35,0.399 -0.35,0.399
  body extent -0.85,-0.45 0.85,0.45, height 0.6
LED_0603_OSRAM_LG-Q396-PS-35_GREEN_1A2K_H0P4 [mm]
  rect 0.8x0.8 smd mask+0.05: 1(-0.75,0) 2(0.75,0)
  Top Layer keep-out region: -0.35,-0.4 0.35,-0.4 0.35,0.4 -0.35,0.4
  body extent -0.85,-0.45 0.85,0.45, height 0.6
LED_0603_OSRAM_LO-Q976-PS-25_ORANGE_1A2K_H0P8 [mm]
  rect 0.8x0.8 smd mask+0.05: 1(-0.75,0) 2(0.75,0)
  Top Layer keep-out region: -0.35,-0.4 0.35,-0.4 0.35,0.4 -0.35,0.4
  body extent -0.85,-0.45 0.85,0.45, height 0.8
LED_0603_VISHAY_VLMS1300-GS08_RED_1A2K_H0P8 [mm]
  rect 0.8x0.8 smd mask+0.05: 1(-0.75,0) 2(0.75,0)
  Top Layer keep-out region: -0.35,-0.399 0.35,-0.399 0.35,0.401 -0.35,0.401
  body extent -0.85,-0.45 0.85,0.45, height 0.8
LED_BI-GR_WE-150141SV73110 [mm] "MCD-02631"
  rect 1.1x1.5 smd mask+0.05: 1(-0.75,1.5) 2(0.75,1.5) 3(-0.75,-1.5) 4(0.75,-1.5)
  silkscreen extent -1.65,-1.85 1.5,1.7, body extent -1.5,-1.85 1.5,1.85, height 2.1
LINK200#1 [mm]
  rect 0.2x0.35 smd paste-10 mask+0.05: 1(0,-0.225) 2(0,0.225)
LINK200#2 [mm]
  rect 0.8x0.35 smd paste-10 mask+0.05: 1(0,-0.225) 2(0,0.225)
MIRE_PLACE_SMD_0P8MM [mm]
  round 0.8 smd paste-10 mask+0.2: 1(0,0)
  Top Layer keep-out circle w0.01: c0,0 r0.804
MOS_SC89-3L [mm] "MCD-02221"
  rect 0.46x0.65 smd mask+0.05: 1(-0.5,-0.55) 2(0.5,-0.55) 3(0,0.55)
  silkscreen extent -0.85,-0.48 0.85,0.48, body extent -0.85,-0.85 0.85,0.85, height 0.85
MOS_SOT23-5L [mm]
  rect 0.6x1.3 smd mask+0.05: 1(-0.95,-1.1) 2(0,-1.1) 3(0.95,-1.1) 4(0.95,1.1) 5(-0.95,1.1)
  silkscreen extent -1.6,-0.95 1.6,0.97, body extent -1.52,-1.25 1.52,1.25, height 1.45
PowerFLAT_5x6 [mm] "MCD-02152"
  rect 0.65x1.25 smd mask+0.05: 1(1.905,2.675) 2(0.635,2.675) 3(-0.635,2.675) 4(-1.905,2.675) 5(-1.905,-2.675) 6(-0.635,-2.675) 7(0.635,-2.675) 8(1.905,-2.675)
  Top Layer region: 0.2,-3.3 0.95,-3.3 0.95,-2.75 1.575,-2.75 1.575,-3.3 2.3,-3.3 2.3,-2.3 2.7,-2.3 2.7,-1.5 2.3,-1.5 2.3,0.15 2.7,0.15 2.7,0.975 2.3,0.975 2.3,1.15 0.2,1.15
  Top Layer region: -0.2,-3.3 -0.95,-3.3 -0.95,-2.75 -1.575,-2.75 -1.575,-3.3 -2.3,-3.3 -2.3,-2.3 -2.7,-2.3 -2.7,-1.5 -2.3,-1.5 -2.3,0.15 -2.7,0.15 -2.7,0.975 -2.3,0.975 -2.3,1.15 -0.2,1.15
  silkscreen extent -2.5,-3 2.5,3, body extent -2.6,-3.08 2.6,3.07, height 1
PTC_BEL-FUSE_1812_0ZCG0260FF2C [mm]
  rect 2.4x3.5 smd mask+0.05: 1(-2.3,0) 2(2.3,0)
  silkscreen extent -1,-1.73 1,1.73, body extent -2.36,-1.71 2.36,1.71, height 1.2
R0201_H0P23 [mm] "MCD-00702"
  rect 0.4x0.5 smd mask+0.05: 1(-0.3,0) 2(0.3,0)
  body extent -0.32,-0.17 0.32,0.17, height 0.26
R0402 [mm]
  rect 0.51x0.7 smd mask+0.05: 1(-0.45,0) 2(0.45,0)
  body extent -0.52,-0.3 0.52,0.3, height 0.4
R0603 [mm]
  rect 0.64x1 smd mask+0.05: 1(-0.7,0) 2(0.7,0)
  silkscreen extent -1.05,-0.58 1.05,0.58, body extent -0.9,-0.5 0.9,0.5, height 0.56
R0805 [mm]
  rect 0.85x1.3 smd mask+0.05: 1(-0.875,0) 2(0.875,0)
  silkscreen extent -0.33,-0.67 0.33,0.67, body extent -1.05,-0.68 1.05,0.68, height 0.65
Sheetbox_6L2S [mil] "Sheetbox 6 layers / 2 silkscreens"
  round 20 on Mech16: 1(813.5,208.05) 1(2736.63,208.05)
SOCKET_MIKROBUS_MIKROE-4319_SMD_P254 [mm] "MCD-03517"
  round 0 hole 1.4 unplated mask+0.05: 0(-12,-10.55) 0(11.2,-10.55)
  rrect20% 3x1.3 smd mask+0.05: 1(-12.88,8.89) 2(-12.88,6.35) 3(-12.88,3.81) 4(-12.88,1.27) 5(-12.88,-1.27) 6(-12.88,-3.81) 7(-12.88,-6.35) 8(-12.88,-8.89) 9(12.88,-8.89) 10(12.88,-6.35) 11(12.88,-3.81) 12(12.88,-1.27) 13(12.88,1.27) 14(12.88,3.81) 15(12.88,6.35) 16(12.88,8.89)
  silkscreen extent -12.7,-12.72 12.7,10.16, body extent -13.72,-12.72 13.74,10.18, height 11.02
SOLDER-BRIDGE_R0402-0R [mil] "MCD-01619"
  round 10 smd paste-393.7: 1(-17.72,0) 2(20.67,0)
  Top Layer region: 1.48,13.78 8.37,0 1.48,-13.78 30.51,-13.78 30.51,13.78
  Top Layer region: -30.51,-13.78 -30.51,13.78 -8.37,13.78 -1.48,0 -8.37,-13.78
  silkscreen extent -33,-17 33,17, body extent -20,-12 20,12, height 14
SOLDER-BRIDGE_R0603-0R [mil]
  round 10 smd paste-393.7: 1(-19.68,0) 2(23.62,0)
  Top Layer region: -47.24,-19.68 -47.24,19.68 -15.75,19.68 3.94,0 -15.75,-19.68
  Top Layer region: -5.91,19.68 13.78,0 -5.91,-19.68 47.24,-19.68 47.24,19.68
  silkscreen extent -50,-23 50,23, body extent -36,-20 36,20, height 22
SWI_GRAYHILL-INC_76SB04ST [mm] "MCD-02256"
  rect 1.5x1.5 hole 0.9 mask+0.05: 1(-3.75,-3.81)
  round 1.5 hole 0.9 mask+0.05: 2(-1.25,-3.81) 3(1.25,-3.81) 4(3.75,-3.81) 5(3.75,3.81) 6(1.25,3.81) 7(-1.25,3.81) 8(-3.75,3.81)
  silkscreen extent -6.1,-4.82 6.1,4.82, body extent -6.1,-4.83 6.1,4.82, height 6.9
SWI_KNITTER_TSS644S [mm] "MCD-02417"
  rect 1.55x1.3 smd mask+0.05: 1(-3.975,2.25) 2(3.975,2.25) 3(-3.975,-2.25) 4(3.975,-2.25)
  silkscreen extent -3.1,-3.1 3.1,3.1, body extent -4.5,-3.1 4.5,3.1, height 7.3
TP_PTH-1P02MM_TEST-TERMINAL_RS_101-2391_BLACK [mm] "MCD-00713"
  round 3 hole 1.1 mask+0.05: 1(0,0)
  silkscreen extent -1.62,-1.63 1.62,1.63, body extent -1.24,-1.25 1.25,1.25, height 4.85
TP_SMD_0-6MM [mm]
  round 0.6 smd paste-10 mask+0.05: 1(0,0)
  silkscreen extent -0.5,-0.5 0.5,0.5
TP_SMD_1MM [mm]
  round 1 smd paste-10 mask+0.05: 1(0,0)
  silkscreen extent -0.7,-0.7 0.7,0.7

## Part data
B1 B4 B5: library part MCD-02417, "Push Button, NO, 0.05A, 12V, 2.6N, SMD, 9.0x6.2mm, T=7.3mm, changeable caps KTSC-6xx", Alternate_Manufacturer=N/A, Manufacturer=KNITTER-SWITCH, Manufacturer_Part_Number=TSS644S, Package=9.0x6.2mm
B2 B3: library part MCD-02417, "Push Button, NO, 0.05A, 12V, 2.6N, SMD, 9.0x6.2mm, T=7.3mm, changeable caps KTSC-6xx", Manufacturer=KNITTER-SWITCH, Manufacturer_Part_Number=TSS644S, Package=9.0x6.2mm
C1 C2 C3 C9 C174: library part MCD-02352, "Capacitor, MLCC, 100nF, 10V, X5R, +/-10%, 0402, T=0,5mm", Manufacturer=YAGEO, Manufacturer_Part_Number=CC0402KRX5R6BB104, Package=0402
C4 C10 C143: library part MCD-00204, "Capacitor, MLCC, 47uF, 10V, X5R, +/-20%, 0805, T=1.25mm", Manufacturer=MURATA, Manufacturer_Part_Number=GRM21BR61A476ME15K, Package=0805
C5 C157 C158 C173: library part MCD-02198, "Capacitor, MLCC, 10nF, 50V, X7R, +/-10%, 0402, T=0.5mm", Manufacturer=YAGEO, Manufacturer_Part_Number=CC0402KRX7R9BB103, Package=0402
C6: library part MCD-01356, "Capacitor, MLCC, 4.7uF, 6V3, X5R, 20%, 0402, T=0,5mm", Alternate_Manufacturer=MURATA, Alternate_Manufacturer_Part_Number=GRM155R60J475ME87, Manufacturer_Part_Number=GRM155R60J475ME47, Package=0402
C7: library part MCD-00095, "Capacitor, MLCC, 1uF, 25V, X5R, +/-10%, 0402, T=0,5mm", Alternate_Manufacturer=MURATA, Alternate_Manufacturer_Part_Number=GRM155R60J105KE19, Manufacturer_Part_Number=GRM155R61E105KA12, Package=C0402
C8 C11 C12 C48 C49 C50 C51 C77 C78 C79 C80 C82 C83 C84 C93 C94 C95 C177 C179 C182 C184 C185 C186 C187 C189 C198 C202 C211 C226 C238 C239 C245 C247 C255 C256 C257 C258 C259 C261 C262 C264: library part MCD-00006, "Capacitor, MLCC, 100nF, 16V, X7R, +/-10%, 0402, T=0.5mm", Alternate_Manufacturer=MURATA, Alternate_Manufacturer_Part_Number=GCM155R71C104KA55D, Manufacturer=YAGEO, Manufacturer_Part_Number=CC0402KRX7R7BB104, Package=0402
C13: library part MCD-00198, "Capacitor, MLCC, 1nF, 16V, X7R, +/-10%, 0402, T=0.5mm", Manufacturer=YAGEO, Manufacturer_Part_Number=CC0402KRX7R7BB102, Package=0402
C14 C15 C62 C69 C96 C100 C101 C102 C119 C128 C146 C149 C155 C163 C175 C273 C275 C276 C281 C282 C283 C284 C285 C289 C290 C297 C298 C299 C303 C310 C311 C324 C325 C326 C327 C328 C329 C333 C334: library part MCD-00006, "Capacitor, MLCC, 100nF, 16V, X7R, +/-10%, 0402, T=0.5mm", Manufacturer=YAGEO, Manufacturer_Part_Number=CC0402KRX7R7BB104, Package=0402
C16 C17 C18 C52 C53 C54 C57 C58 C59 C60: library part MCD-03139, "Capacitor, MLCC, 22uF, 10V, X5R, +/-20%, 0805, T=1,25mm", Manufacturer=MURATA, Manufacturer_Part_Number=GRM21BR61A226ME51L, Package=0805
C19 C20 C21 C22 C23 C24 C25 C26 C27 C28 C31 C33 C34 C35 C36 C37 C41 C44 C47 C55: library part MCD-00100, "Capacitor, MLCC, 22uF, 6V3, X5R, +/-20%, 0603, T=0,8mm", Alternate_Manufacturer=N/A, Manufacturer=MURATA, Manufacturer_Part_Number=GRM188R60J226MEA0J, Package=0603
C29 C30 C32 C38 C45 C46 C56: library part MCD-00099, "Capacitor, MLCC, 10uF, 10V, X5R, +/-10%, 0603, T=0,8mm", Alternate_Manufacturer=N/A, Manufacturer=MURATA, Manufacturer_Part_Number=GRM188R61A106KE69D, Package=0603
C39 C40 C176: library part MCD-03140, "Capacitor, MLCC, 10uF, 6.3V, X5R, +/-20%, 0402, T=0.5mm", Manufacturer=MURATA, Manufacturer_Part_Number=GRM155R60J106ME05D, Package=0402
C42 C147: library part MCD-01796, "Capacitor, Tantalum, 100uF, 6V3, 40mR, +/-20%,  Type_B (3528 metric), T=1.9mm", Manufacturer=AVX, Manufacturer_Part_Number=TCJB107M006R0040, Package="3528 (metric)"
C43: library part MCD-01722, "Capacitor, MLCC, 1uF, 10V, X5R, +/-10%, 0402, T=0.5mm", Alternate_Manufacturer=N/A, Manufacturer=YAGEO, Manufacturer_Part_Number=CC0402KRX5R6BB105, Package=0402
C61 C63 C65 C66 C68 C72 C73 C74 C75 C277 C335: library part MCD-01356, "Capacitor, MLCC, 4.7uF, 6V3, X5R, +/-20%, 0402, T=0.5mm", Manufacturer=MURATA, Manufacturer_Part_Number=GRM155R60J475ME47, Package=0402
C64 C67 C70: library part MCD-00095, "Capacitor, MLCC, 1uF, 25V, X5R, +/-10%, 0402, T=0.5mm", Manufacturer=MURATA, Manufacturer_Part_Number=GRM155R61E105KA12, Package=0402
C71: library part MCD-00097, "Capacitor, MLCC, 4.7uF, 16V, X5R, +/-20%, 0603, T=0.8mm", Manufacturer=MURATA, Manufacturer_Part_Number=GRM188R61C475KE11, Package=0603
C76 C89 C129 C165 C169 C183 C254: library part MCD-00099, "Capacitor, MLCC, 10uF, 10V, X5R, +/-10%, 0603, T=0.8mm", Manufacturer=MURATA, Manufacturer_Part_Number=GRM188R61A106KE69D, Package=0603
C81 C86 C90 C92: library part MCD-00674, "Capacitor, MLCC, 6.8pF, 50V, NPO, +-0.25pF, 0402, T=0.5mm", Alternate_Manufacturer=N/A, Manufacturer=YAGEO, Manufacturer_Part_Number=CC0402CRNPO9BN6R8, Package=0402
C85 C99 C188 C236: library part MCD-01341, "Capacitor, MLCC, 10uF, 6V3, X5R, +/-20%, 0603, T=0,8mm", Alternate_Manufacturer=MURATA, Alternate_Manufacturer_Part_Number=GRM188R60J106ME84D, Manufacturer_Part_Number=GRM188R60J106ME47D, Package=0603
C87 C103 C104 C105 C106 C107 C108 C109 C123 C124 C125 C141 C142 C144 C152 C153 C154 C270 C271 C291 C292 C293 C294 C295 C296 C304 C305 C306 C307 C308 C309 C312 C313 C314 C315 C316 C317 C318 C319 C320 C321 C322 C323: library part MCD-00006, "Capacitor,100nF,16V,X7R,10%,0402", Alternate_Manufacturer=MURATA, Alternate_Manufacturer_Part_Number=GCM155R71C104KA55D, Manufacturer=YAGEO, Manufacturer_Part_Number=CC0402KRX7R7BB104, Package=0402
C88: library part MCD-01823, "Capacitor, MLCC, 2.2uF, 6V3, X5R,+/-10%, 0402, T=0.5mm", Alternate_Manufacturer=N/A, Manufacturer=MURATA, Manufacturer_Part_Number=GRM155R60J225KE95D, Package=0402
C91: library part MCD-00011, "Capacitor, MLCC, 10nF, 16V, X7R, 10%, 0402, T=0.5mm", Alternate_Manufacturer=N/A, Manufacturer=YAGEO, Manufacturer_Part_Number=CC0402KRX7R7BB103, Package=0402
C97 C98: library part MCD-01535, "Capacitor, MLCC,100nF, 10V, X7R, +/-10%, 0201, T=0.3mm", Manufacturer=MURATA, Manufacturer_Part_Number=GRM033R61A104KE15, Package=0201
C110 C159: library part MCD-02372, "Capacitor, MLCC, 2.2uF, 25V, X7R, +/-10%, 0805, T=1,25mm", Manufacturer=MURATA, Manufacturer_Part_Number=GRM21BR71E225KE11L, Package=0805
C111 C112 C113 C120 C121 C122 C278 C279 C280 C286 C287 C288 C300 C301 C302 C330 C331 C332: library part MCD-00100, "Capacitor,22uF,6V3,X5R,20%,0603", Manufacturer=MURATA, Manufacturer_Part_Number=GRM188R60J226MEA0J, Package=0603
C114 C118: library part MCD-00204, "Capacitor, MLCC, 47uF, 10V, X5R, +/-20%, 0805, T=1,25mm", Alternate_Manufacturer=N/A, Manufacturer=MURATA, Manufacturer_Part_Number=GRM21BR61A476ME15K, Package=0805
C115 C126: library part MCD-00674, "Capacitor, MLCC, 6.8pF, 50V, NPO, +/-0.25pF, 0402, T=0.5mm", Manufacturer=YAGEO, Manufacturer_Part_Number=CC0402CRNPO9BN6R8, Package=0402
C116: library part MCD-01525, "Capacitor, MLCC, 100nF, 50V, X7R, 10%, 0805, T=0,85mm", Alternate_Manufacturer=N/A, Manufacturer=YAGEO, Manufacturer_Part_Number=CC0805KRX7R9BB104, Package=0805
C117 C148: library part MCD-00014, "Capacitor, MLCC, 10uF, 25V, X5R, +/-10%, 0805, T=0,85mm", Alternate_Manufacturer=N/A, Manufacturer=YAGEO, Manufacturer_Part_Number=CC0805KRX5R8BB106, Package=0805
C127: library part MCD-01683, "Capacitor,Electrolytic,100uF,35V, 20%, SMT, D=8mm, T=10.5mm", Alternate_Manufacturer=N/A, Manufacturer="WURTH ELEKTRONIK", Manufacturer_Part_Number=865060553006, Package=8x10.5mm
C130: library part MCD-01995, "Capacitor, MLCC, 22pF, 50V, C0G, 5%, 0402, T=0,5mm", Alternate_Manufacturer=N/A, Manufacturer=TDK, Manufacturer_Part_Number=C1005NP01H220J050BA, Package=0402
C131: library part MCD-00016, "Capacitor, MLCC, 20pF, 50V, NPO, +/- 5%, 0402, T=0.5mm", Manufacturer=YAGEO, Manufacturer_Part_Number=CC0402JRNPO9BN200, Package=0402
C132 C145 C160 C178 C180 C181: library part MCD-02606, "Capacitor, MLCC, 2.2uF, 6.3V, X5R, +/-10%, 0402, T=0.5mm", Manufacturer=YAGEO, Manufacturer_Part_Number=CC0402KRX5R5BB225, Package=0402
C133 C140: library part MCD-01774, "Capacitor, MLCC, 2.7pF, 50V, NPO, +/-0.1pF, 0402, T=0.5mm", Manufacturer=YAGEO, Manufacturer_Part_Number=CC0402BRNPO9BN2R7, Package=0402
C134 C135 C136 C137 C138 C139: library part MCD-00015, "Capacitor,10pF,50V,NPO,5%,0402", Manufacturer=YAGEO, Manufacturer_Part_Number=CC0402JRNPO9BN100, Package=0402
C150 C161: library part MCD-00104, "Capacitor, MLCC, 220uF, 6V3, X5R, +/-20%, 1206, T=1.6mm", Manufacturer=MURATA, Manufacturer_Part_Number=GRM31CR60J227ME11, Package=1206
C151: library part MCD-00205, "Capacitor,MLCC,100pF,50V,NPO,+/-5%,0402,T=0,5mm", Alternate_Manufacturer=N/A, Manufacturer=YAGEO, Manufacturer_Part_Number=CC0402JRNPO9BN101, Package=0402
C156 C164: library part MCD-00205, "Capacitor, MLCC, 100pF, 50V, NPO, +/-5%, 0402, T=0.5mm", Manufacturer=YAGEO, Manufacturer_Part_Number=CC0402JRNPO9BN101, Package=0402
C162: library part MCD-01995, "Capacitor, MLCC, 22pF, 50V, C0G, +/-5%, 0402, T=0.5mm", Manufacturer=TDK, Manufacturer_Part_Number=C1005NP01H220J050BA, Package=0402
C166 C172: library part MCD-02355, "Capacitor, MLCC, 100nF, 25V, X7R, +/-10%, 0402, T=0.5mm", Manufacturer=WALSIN, Manufacturer_Part_Number=0402B104K250CT, Package=0402
C168 C171: library part MCD-00724, "Capacitor, MLCC, 470pF, 50V, NPO, +/-5%, 0402, T=0.5mm", Manufacturer=YAGEO, Manufacturer_Part_Number=CC0402JRNPO9BN471, Package=0402
C170: library part MCD-01099, "Capacitor, MLCC, 100nF, 50V, X7R, +/-10%, 0603, T=0.8mm", Manufacturer=YAGEO, Manufacturer_Part_Number=CC0603KRX7R9BB104, Package=0603
C190 C191 C192 C193 C194 C195 C196 C197 C201 C205 C206 C212 C234 C244 C246 C248 C249 C251 C252 C253 C260: library part MCD-01535, "Capacitor, MLCC,100nF, 10V, X7R, +/-10%, 0201, T=0.3mm", Alternate_Manufacturer=N/A, Manufacturer=MURATA, Manufacturer_Part_Number=GRM033R61A104KE15, Package=0201
C199 C200 C203 C204 C207 C208 C209 C210 C213 C214 C215 C216 C217 C218 C219 C220 C221 C222 C223 C224 C227 C228 C229 C230 C231 C232 C233 C237 C240 C241 C242 C243 C250: library part MCD-02377, "Capacitor, MLCC, 1uF, 6.3V, X5R, +/-20%, 0201, T=0,3mm", Alternate_Manufacturer=N/A, Manufacturer=MURATA, Manufacturer_Part_Number=GRM033R60J105MEA2, Package=0201
C225: library part MCD-01534, "Capacitor, MLCC, 4,7uF, 6V3, X5R, +/-20%, 0201, T=0.5mm", Alternate_Manufacturer=N/A, Manufacturer=MURATA, Manufacturer_Part_Number=GRM035R60J475ME15, Package=0201
C235: library part MCD-02235, "Capacitor, MLCC, 2.2uF, 10V, X5R,+/-10%, 0201, T=0.5mm", Manufacturer=MURATA, Manufacturer_Part_Number=GRM033R61A225KE47D, Package=0201
C265 C266 C267 C268 C269 C272 C274: library part MCD-00697, "Capacitor, MLCC, 100nF,10V, X5R, +/-10%, 0201, T=0.3mm", Manufacturer=TDK, Manufacturer_Part_Number=C0603X5R1A104K030BC, Package=0201
C336: library part MCD-00011, "Capacitor, MLCC, 10nF, 16V, X7R, 10%, 0402, T=0.5mm", Manufacturer=YAGEO, Manufacturer_Part_Number=CC0402KRX7R7BB103, Package=C0402
CN1: library part MCD-00653, "Connector_uSD Card, Top Mnt Push-Push", Manufacturer=ATOM
CN2: library part MCD-03562, "Socket_FFC/FPC, 40pins, 0.5mm, RA, SMD, T=1mm", Manufacturer=I-PEX, Manufacturer_Part_Number=20455-040E-76
CN3: library part MCD-00137, "Socket, 30x2, 0.5mm, VR, SMD, T=3.05mm", Manufacturer=SAMTEC, Manufacturer_Part_Number=QSH-030-01-F-D-A
CN4: library part MCD-03600, "Socket_FFC/FPC, 22pins, 0.5mm, RA, SMD, T=2mm", Manufacturer="TE CONNECTIVITY"
CN5: library part MCD-00302, "Header, 20x2, 2.54mm, VR, TH, T=5.84mm/2.54mm", Manufacturer=SAMTEC, Manufacturer_Part_Number=TSW-120-07-G-D
CN6 CN7 CN8: library part MCD-00032, "Header, 2x1, 2,54mm, VR, TH, Height 5.84mm/2.54mm", Alternate_Manufacturer=JIUBABA, Alternate_Manufacturer_Part_Number=313102S111116, Manufacturer=SAMTEC, Manufacturer_Part_Number=TSW-102-07-G-S
CN9 CN11: library part MCD-01978, "Connector_DB9-Male, 9pins, 1.39mm, RA, TH, T= 13.575mm/3.8mm", Manufacturer="TE CONNECTIVITY", Manufacturer_Part_Number=2301843-2, Package=TH
CN10: library part MCD-02123, "Header, 7x2, 2,54mm, VR, TH, Height 5.84mm/2.54mm", Alternate_Manufacturer=N/A, Manufacturer=SAMTEC, Manufacturer_Part_Number=TSW-107-07-G-D
CN12: library part MCD-00655, "Header 2 circuits, 1.25mm Pitch ,  Vertical, with Friction Lock", Alternate_Manufacturer=N/A, Manufacturer=MOLEX, Manufacturer_Part_Number=53047-0210
CN13: library part MCD-02227, "Socket_Mini PCIE, 52 pins, RA, SMD, T=4mm", Manufacturer="TE CONNECTIVITY", Manufacturer_Part_Number=2041119-1
CN14: library part MCD-00029, "Header, 4x1, 2.54mm, VR, TH, T=5.84mm/2.54mm", Manufacturer=SAMTEC, Manufacturer_Part_Number=TSW-104-07-G-S
CN15 CN21: library part MCD-03232, "USB_TypeC, 24 pins, RA, SMD, T=2.96mm", Manufacturer="AMPHENOL ICC", Manufacturer_Part_Number=12401826E412A
CN16 CN17 CN18: library part MCD-01129, "Connector_RJ45, led pull down, T= 13.84mm", Manufacturer="YUAN DEAN SCIENTIFIC", Manufacturer_Part_Number=48F-01GYDXNL
CN19: library part MCD-00109, "USB_Dual-TypeA, Receptacle, 8pins, 2.5mm, RA, TH, T= 15.5mm", Manufacturer=CONEXCON, Manufacturer_Part_Number=5600-3081
CN20: library part MCD-00173, "DC-Power-Jack, 2.5mm, 5A, RA, TH", Alternate_Manufacturer=N/A, Manufacturer=CLIFF
CN22: library part MCD-01951, "Header, 5x2, 1.27mm, VR, SMD, T=5.97mm", Manufacturer=SAMTEC, Manufacturer_Part_Number=FTSH-105-01-L-DV-K-A, Package=SMT
CN25: library part MCD-03517, "Socket , mikroBUS , 16 , SMD , Gray", Manufacturer=MIKROE
D1 D5: library part MCD-00034, Manufacturer=STMICROELECTRONICS, Manufacturer_HQ_COO=EU
D2 D3: library part MCD-03011, "Signal Schottky Diode, If=1A, Ifsm=5A, Vf =0.54V@1A, Vrrm=23V, Ir = 0.65µA@5V, SOD-323", Manufacturer=STMICROELECTRONICS, Manufacturer_Part_Number=BAT20JFILM, Package=SOD-323
D6: library part MCD-03280, "Diode, Schottky, Dual Common Cathode, 0V3, 300mA, 40V, SOT-23", Manufacturer=STMICROELECTRONICS, Manufacturer_Part_Number=BAT54CFILM, Package=SOT-23
F1: library part MCD-00624, "SMD, PTC resettable fuse, IH:2.6A, IT:5A, Vdc_max:8V, Rmax:47mohm, BELFUSE", Manufacturer=BELFUSE
JP1 JP2: library part MCD-00045, "Header, 2x1, 2,54mm, VR, TH, Height 5.84mm/2.54mm", Alternate_Manufacturer="JIUBABA; LIANYI", Alternate_Manufacturer_Part_Number=313102S111116;313102S111116, Manufacturer=SAMTEC, Manufacturer_Part_Number=TSW-102-07-G-S
JP3: library part MCD-00045, "Header, 2x1, 2.54mm, VR, TH, T=5.84mm/2.54mm", Manufacturer=SAMTEC, Manufacturer_Part_Number=TSW-102-07-G-S
JP4: library part MCD-00111, "Header, 3x1, 2.54mm, VR, TH, T=5.84mm/2.54mm", Manufacturer=SAMTEC, Manufacturer_Part_Number=TSW-103-07-F-S
L1 L6: library part MCD-03143, "Inductor, 2.2uH, +/-20%, Itemp= 1700mA, Isat= 2400mA, 0R140, 0806, T=1mm", Manufacturer=MURATA, Manufacturer_Part_Number=DFE201610E-2R2M{}P2, Package=0806
L2 L4: library part MCD-03142, "Inductor, 0.68uH, +/-20%, Itemp= 3900mA, Isat= 5400mA, 0R031, 1008, T=1.2mm", Manufacturer=MURATA, Manufacturer_Part_Number=DFE252012F-R68M{}P2, Package=1008
L3 L5 L7: library part MCD-03141, "Inductor, 0.68uH, +/-20%, Itemp= 3100mA, Isat= 4300mA, 0R043, 0806, T=1mm", Manufacturer=MURATA, Manufacturer_Part_Number=DFE201610E-R68M{}P2, Package=0806
L8: library part MCD-02220, "Fixed Inductors WE-LQS 5040 3.3uH 3.4A 24mOhm", Alternate_Manufacturer=N/A, Manufacturer="WURTH ELEKTRONIK", Manufacturer_Part_Number=74404054033, Package=5040
L9 L10 L11 L13 L14 L15: library part MCD-00094, "Ferrite bead 100R 2A 0603", Manufacturer=MURATA, Manufacturer_Part_Number=BLM18EG101TN1, Package=0603
L12: library part MCD-00305, "Ferrite bead, 26R @ 100Mhz, +/-25%, 6000mA, 0R007, 0603, T=0.75mm", Manufacturer=MURATA, Manufacturer_Part_Number=BLM18KG260TN1, Package=0603
LD1 LD12: library part MCD-00587, "LED Red, 0603 SMD, 2V Forward Voltage", Alternate_Manufacturer="OSRAM OPTO SEMICONDUCTORS", Alternate_Manufacturer_Part_Number="LS Q976-NR-1", Manufacturer=VISHAY, Manufacturer_Part_Number=VLMS1300-GS08, Package="LED 0603"
LD2 LD7 LD8 LD9 LD10 LD11: library part MCD-00588, "LED Green, 0603 SMD, Forward Voltage Typ=2V, Max=2.5V", Alternate_Manufacturer="VISHAY SEMICONDUCTOR OPTO DIVISION", Alternate_Manufacturer_Part_Number=VLMTG1300-GS08, Manufacturer="OSRAM OPTO SEMICONDUCTORS", Manufacturer_Part_Number="LG Q396-PS-35", Package="LED 0603"
LD3: library part MCD-00590, "LED Orange, 0603 SMD, Forward Voltage Min=1.6V, Max=2.4V", Alternate_Manufacturer="VISHAY SEMICONDUCTOR OPTO DIVISION", Alternate_Manufacturer_Part_Number=VLMO1300-GS08, Manufacturer="OSRAM OPTO SEMICONDUCTORS", Manufacturer_Part_Number="LO Q976-PS-25", Package="LED 0603"
LD4 LED2: library part MCD-00585, "LED Blue, 0603 SMD, Forward Voltage Min=2,8V, Max=3,8V", Alternate_Manufacturer=EVERLIGHT, Alternate_Manufacturer_Part_Number=19-217-BHC-ZL1M2RY-3T-V4, Manufacturer="OSRAM OPTO SEMICONDUCTORS", Manufacturer_Part_Number="LB Q39G-L2OO-35-1", Package="LED 0603"
LD5 LD6: library part MCD-02631, "LED Bicolor, Green/Red, 2V, 20mA,  4-PLCC", Manufacturer="WURTH ELEKTRONIK", Manufacturer_Part_Number=150141SV73110, Package=4-PLCC
LE1 LE2 LE3: library part MCD-00048, "FIXED IND 4.7UH 1A 180 MOHM 30% SMD", Manufacturer=MURATA, Manufacturer_Part_Number=LQH32PN4R7NN0L, Package=1210
LNK1 LNK2 LNK3 LNK4 LNK5 LNK6 LNK7 LNK8 LNK9 LNK10 LNK11 LNK12: "link 0.2mm"
LNK13: library part MCD-02777, "Track link on PCB 200um width for layout routing. No component assembly and no component in BOM", Manufacturer=N/A
Q1 Q2 Q3: library part MCD-02221, "MOSFET N-CH 20V SC-89", Alternate_Manufacturer=N/A, Manufacturer=VISHAY, Manufacturer_Part_Number=Si1062X, Package=SC-89
Q4: library part MCD-02221, "MOSFET N-CH 20V SC-89", Manufacturer=VISHAY, Manufacturer_Part_Number=Si1062X, Package=SC-89
Q5: library part MCD-02152, "MOSFET, Dual N-channel 30 V, 0.016 Ω typ., 40 A, STripFET™ H5 Power MOSFET", Manufacturer=STMICROELECTRONICS, Manufacturer_HQ_COO=EU, Package="PowerFLAT 5x6"
R1 R9 R91 R103 R104 R106 R156 R157 R213 R214 R215 R220 R223 R323 R324: library part MCD-00053, "Resistor, 10K, 0402, +/-1%, 1/16W", Manufacturer=YAGEO, Manufacturer_Part_Number=RC0402FR-0710KL, Package=0402
R2 R18 R67 R77 R78 R87 R88 R89 R90 R92 R129 R154 R155 R211 R212 R290 R291: library part MCD-00052, "Resistor, 0R, 0402, +/-5%, 1/16W", Manufacturer=YAGEO, Manufacturer_Part_Number=RC0402JR-070RL, Package=0402
R3: library part MCD-00461, "Resistor,360R,0402,1%,1/16W", Manufacturer=YAGEO, Manufacturer_Part_Number=RC0402FR-07360RL, Package=0402
R4 R171: library part MCD-00194, "Resistor,120R,0402,1%,1/16W", Manufacturer=YAGEO, Manufacturer_Part_Number=RC0402FR-07120RL, Package=0402
R5: library part MCD-00179, "Resistor, 0R, 0805, +/-5%, 1/8W", Manufacturer=YAGEO, Manufacturer_Part_Number=RC0805JR-070RL, Package=0805
R6 R21 R22 R38 R46 R52 R57 R59 R60 R61 R64 R75 R267 R269 R286 R288 R326 R328: library part MCD-00052, "Resistor,0R,0402,5%,1/16W", Alternate_Manufacturer=N/A, Manufacturer=YAGEO, Manufacturer_Part_Number=RC0402JR-070RL, Package=0402
R7 R13 R27 R74 R96 R107 R125 R205 R206 R252 R272: library part MCD-00053, "Resistor,10K,0402,1%,1/16W", Alternate_Manufacturer=N/A, Manufacturer=YAGEO, Manufacturer_Part_Number=RC0402FR-0710KL, Package=0402
R8 R16 R17 R24 R25: library part MCD-00059, "Resistor,100K,0402,1%,1/16W", Alternate_Manufacturer=YAGEO, Alternate_Manufacturer_Part_Number=RT0402FRE07100KL, Manufacturer_Part_Number=RC0402FR-07100KL, Package=0402
R10 R11 R12 R14 R15 R226 R230: library part MCD-00063, "Resistor,47K,0402,1%,1/16W", Alternate_Manufacturer=N/A, Manufacturer=YAGEO, Manufacturer_Part_Number=RC0402FR-0747KL, Package=0402
R19: library part MCD-00449, "Resistor,300R,0402,1%,1/16W", Manufacturer=YAGEO, Manufacturer_Part_Number=RC0402FR-07300RL, Package=0402
R20 R126 R127 R128 R172 R210: library part MCD-00441, "Resistor,270R,0402,1%,1/16W", Manufacturer=YAGEO, Manufacturer_Part_Number=RC0402FR-07270RL, Package=0402
R23 R33: library part MCD-00053, "Resistor,10K,0402,1%,1/16W", Manufacturer=YAGEO, Manufacturer_Part_Number=RC0402FR-0710KL, Package=R0402
R26 R181: library part MCD-00067, "Resistor, 100R, 0402, +/- 1%, 1/16W", Manufacturer=YAGEO, Manufacturer_Part_Number=RC0402FR-07100RL, Package=0402
R28 R29: library part MCD-00062, "Resistor,330R,0402,1%,1/16W", Alternate_Manufacturer=N/A, Manufacturer=YAGEO, Manufacturer_Part_Number=RC0402FR-07330RL, Package=0402
R30 R101: library part MCD-00061, "Resistor, 1K, 0402, +/-1%,1/16W", Manufacturer=YAGEO, Manufacturer_Part_Number=RC0402FR-071KL, Package=0402
R31 R32 R224 R228 R245 R246: library part MCD-00068, "Resistor,1K5,0402,1%,1/16W", Alternate_Manufacturer=N/A, Manufacturer=YAGEO, Manufacturer_Part_Number=RC0402FR-071K5L, Package=0402
R34 R37 R44 R49 R81 R248: library part MCD-00053, "Resistor,10K,0402,1%,1/16W", Manufacturer=YAGEO, Manufacturer_Part_Number=RC0402FR-0710KL, Package=0402
R35 R36 R39 R45 R47 R53: library part MCD-00181, "Resistor,0R,0603,ULO", Alternate_Manufacturer=N/A, Manufacturer=ROHM, Manufacturer_Part_Number=PMR03EZPJ000, Package=0603
R40 R80: library part MCD-00194, "Resistor, 120R, 0402, +/-1%, 1/16W", Manufacturer=YAGEO, Manufacturer_Part_Number=RC0402FR-07120RL, Package=0402
R41 R54: library part MCD-03197, "Resistor, 330mR, 0603, +/-1%, 1/5W", Manufacturer=YAGEO, Manufacturer_Part_Number=PT0603FR-7W0R33L, Package=0603
R42 R51: library part MCD-03229, "Resistor, 33mR, 0603, +/-1%, 1/4W", Manufacturer=PANASONIC, Manufacturer_Part_Number=ERJ-3BWFR033V, Package=0603
R43 R48: library part MCD-02234, "Resistor,100moHm,0603,1%,1/3W", Alternate_Manufacturer=N/A, Manufacturer=PANASONIC, Manufacturer_Part_Number=ERJ-3BWFR100V, Package=0603
R50 R86: library part MCD-00061, "Resistor,1K,0402,1%,1/16W", Manufacturer=YAGEO, Manufacturer_Part_Number=RC0402FR-071KL, Package=0402
R55 R56 R69: library part MCD-00056, "Resistor,0R,0603,5%,1/10W", Alternate_Manufacturer=N/A, Manufacturer=YAGEO, Manufacturer_Part_Number=RC0603JR-070RL, Package=0603
R58: library part MCD-00181, "Resistor, 0R, 0603, +/- 0.5mR, 1/4W", Alternate_Manufacturer=N/A, Manufacturer=ROHM, Manufacturer_Part_Number=PMR03EZPJ000, Package=0603
R62: library part MCD-00531, "Resistor, 82K, 0402, +/-1%, 1/16W", Manufacturer=YAGEO, Manufacturer_Part_Number=RC0402FR-0782KL, Package=0402
R63 R73 R262: library part MCD-02253, "Resistor,240R,0201,1%,1/20W", Alternate_Manufacturer=N/A, Manufacturer=YAGEO, Manufacturer_Part_Number=RC0201FR-07240RL, Package=R0201
R65: library part MCD-00344, "Resistor, 19K6, 0402, +/-1%, 1/16W", Manufacturer=YAGEO, Manufacturer_Part_Number=RC0402FR-0719K6L, Package=0402
R66: library part MCD-00058, "Resistor, 20R, 0402, +/-1%, 1/16W", Alternate_Manufacturer=N/A, Manufacturer=YAGEO, Manufacturer_Part_Number=RC0402FR-0720RL, Package=0402
R68 R71 R72 R76 R79: library part MCD-00061, "Resistor,1K,0402,1%,1/16W", Alternate_Manufacturer=N/A, Manufacturer=YAGEO, Manufacturer_Part_Number=RC0402FR-071KL, Package=0402
R70: library part MCD-00358, "Resistor,10R,0402,1%,1/16W", Alternate_Manufacturer=N/A, Manufacturer=YAGEO, Manufacturer_Part_Number=RC0402FR-0710RL, Package=0402
R82 R83 R84 R85: library part MCD-00565, "Resistor, 49R9, 0402, +/-1%, 1/16W", Manufacturer=YAGEO, Manufacturer_Part_Number=RC0402FR-0749R9L, Package=0402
